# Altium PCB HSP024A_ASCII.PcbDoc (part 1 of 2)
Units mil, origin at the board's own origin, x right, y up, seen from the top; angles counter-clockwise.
Board outline 1350 x 2125 mil, 4 copper layers (Top Layer L1, GND L2, Power L3, Bottom Layer L4), stack 61.668 mil thick; 54 components, 18 nets, 93 pads, 271 vias.
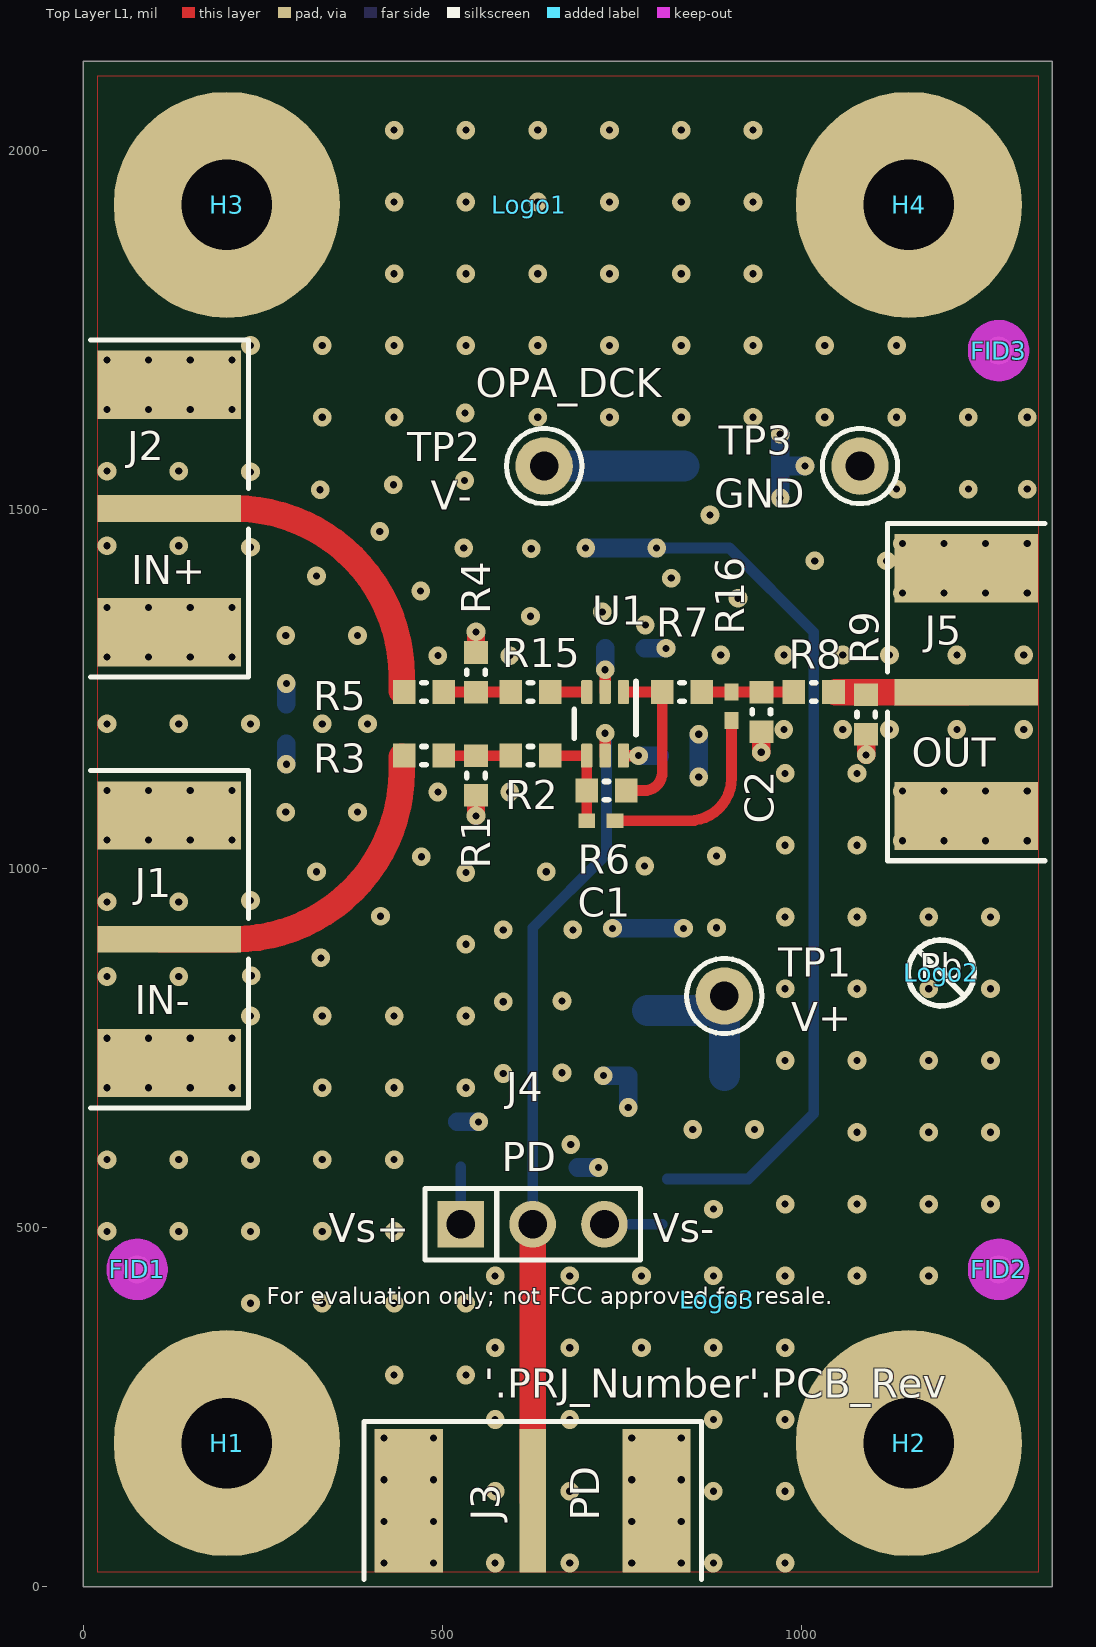
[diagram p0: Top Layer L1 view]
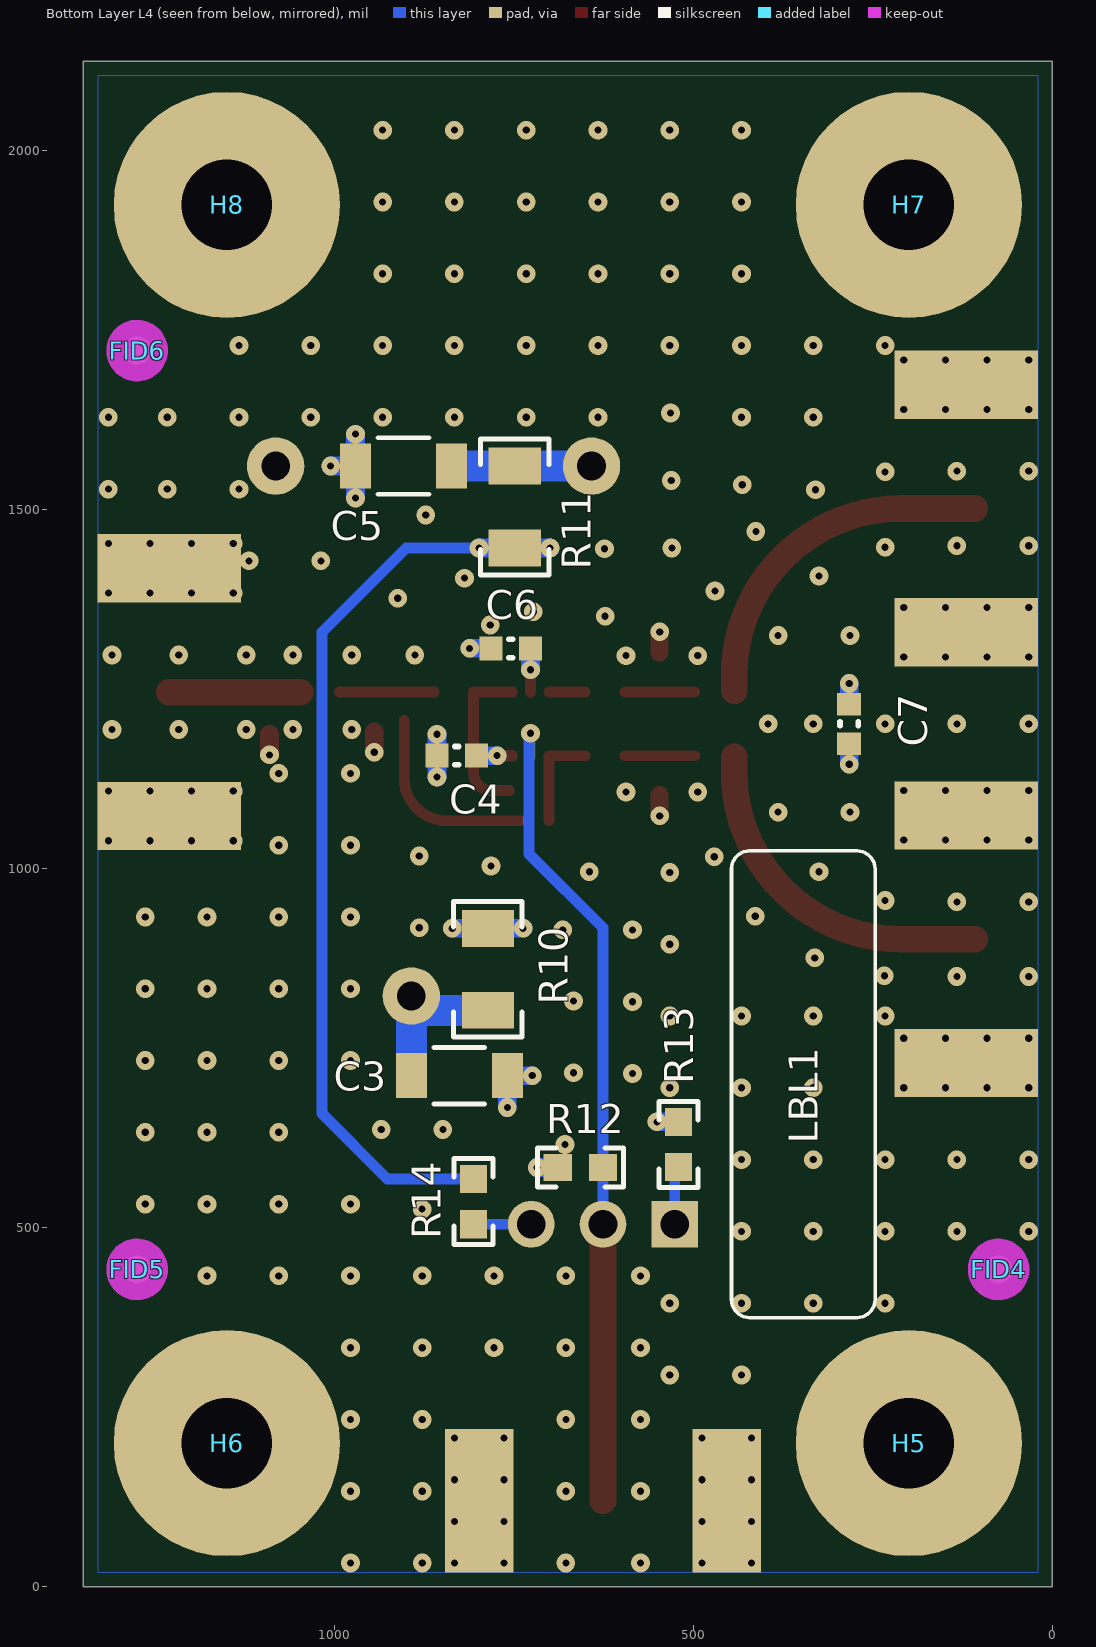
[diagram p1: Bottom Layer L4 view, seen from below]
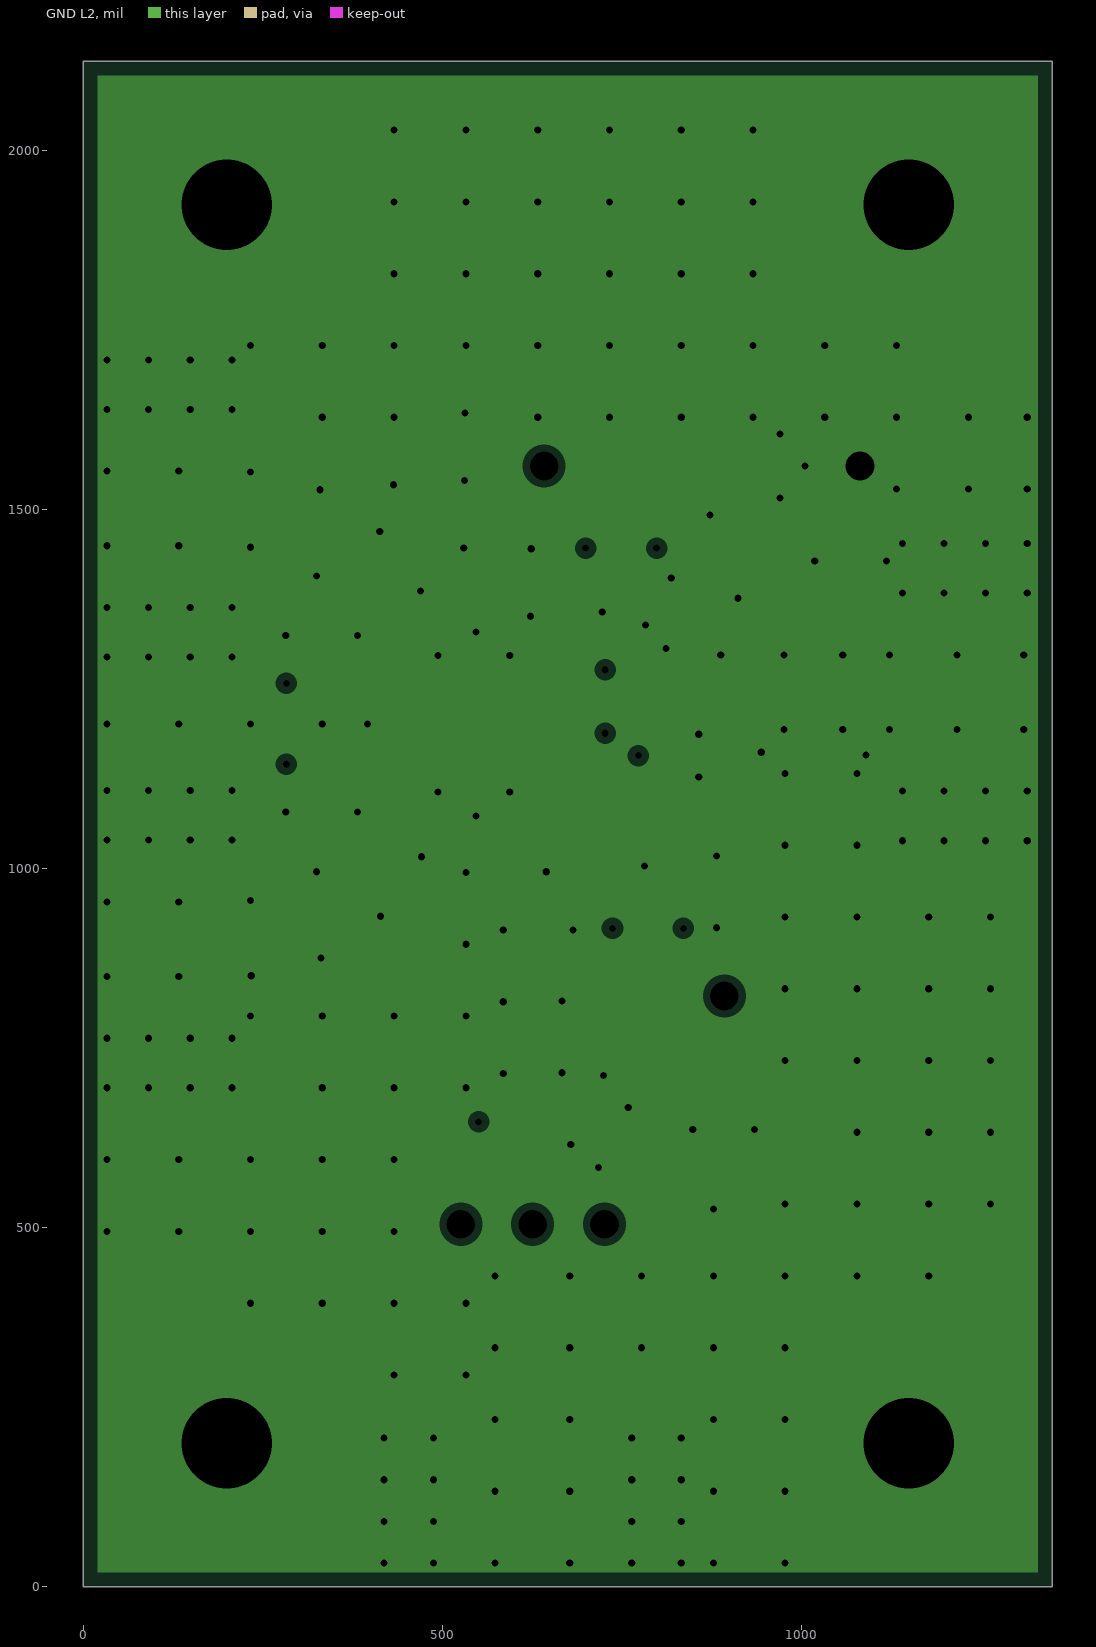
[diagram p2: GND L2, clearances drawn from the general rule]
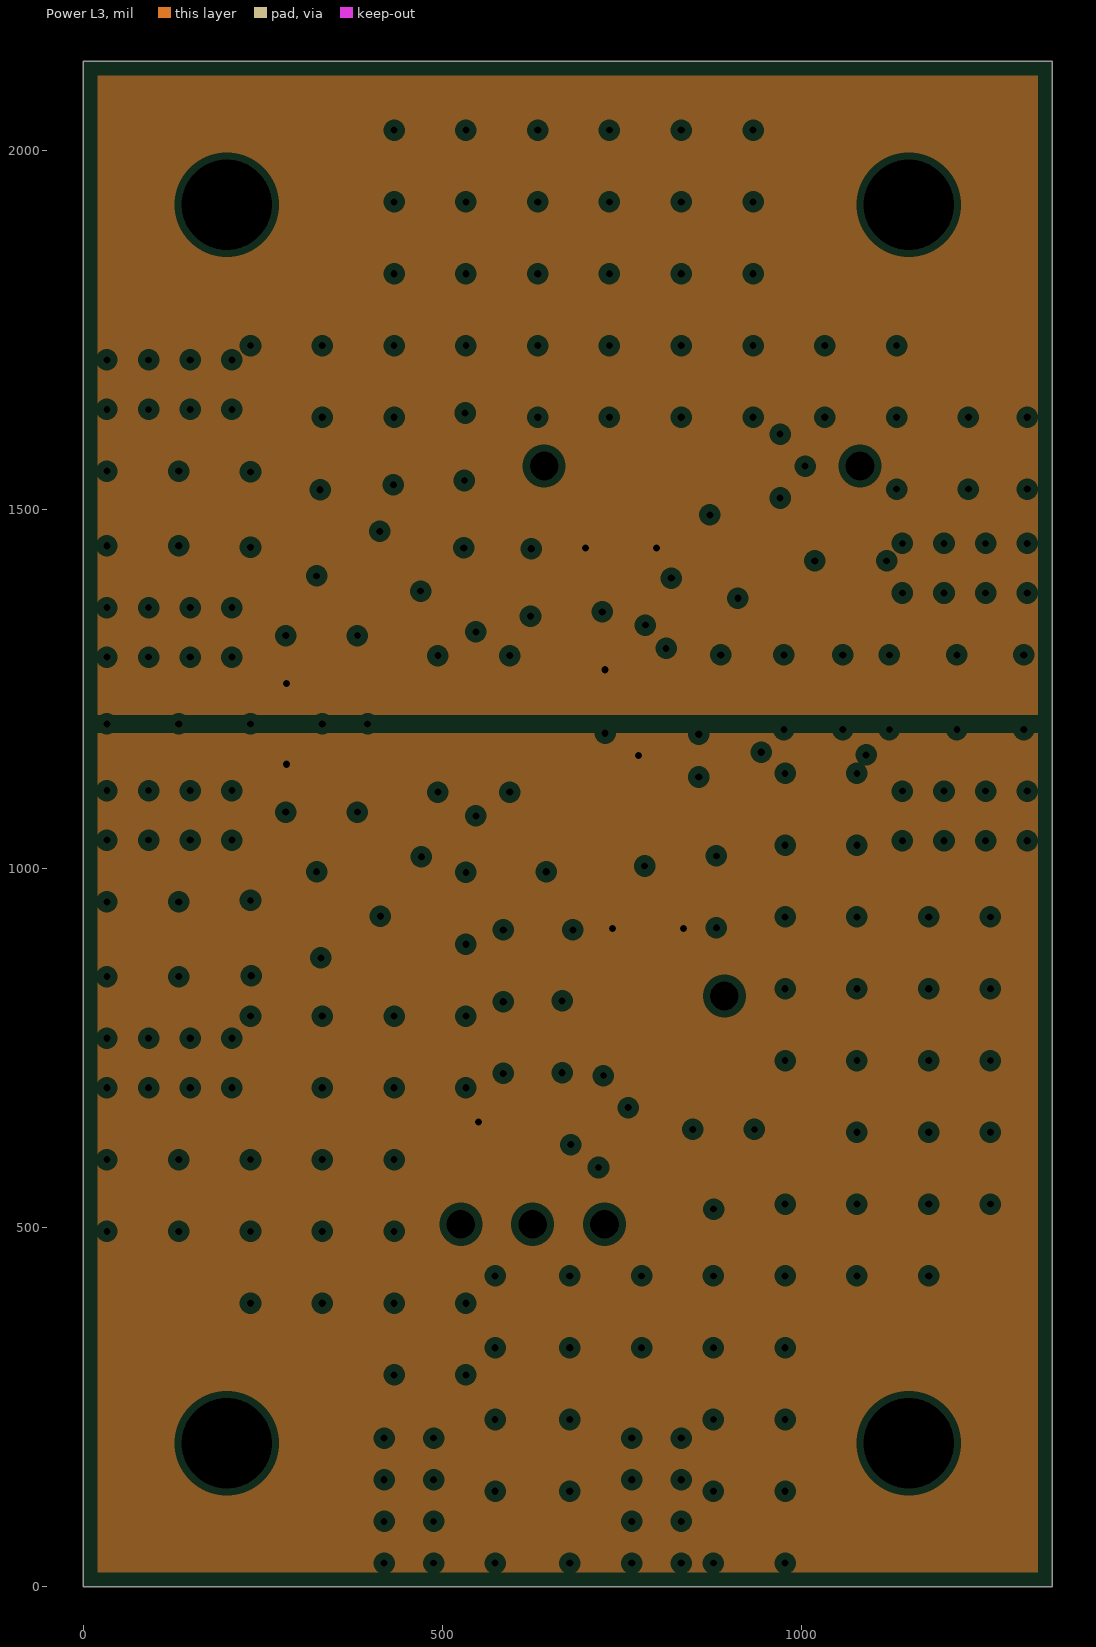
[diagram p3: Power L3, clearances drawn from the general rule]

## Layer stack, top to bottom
Top Solder: solder mask 0.4, Solder Resist, Dk 3.5
Top Layer L1: signal copper 1.417
Dielectric 1: core 21, FR-406, Dk 4.6
GND L2: plane copper 1.417, net GND
Dielectric4: prepreg 14, FR-406, Dk 4.6
Power L3: plane copper 1.417, net VS+
Dielectric5: core 21, FR-406, Dk 4.6
Bottom Layer L4: signal copper 1.417
Bottom Solder: solder mask 0.4, Solder Resist, Dk 3.5

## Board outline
0,0 1350,0 1350,2125 0,2125

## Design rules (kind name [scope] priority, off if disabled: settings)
AcuteAngle [All] p0: scope1count=1 scope1_0_kind=Board scope1_0_value=Board scope2count=1 scope2_0_kind=Board scope2_0_value=Board commentlength=0 minimum=4.50000000000000E+0001
AcuteAngle [All] p1: minimum=4.50000000000000E+0001 checktracksonly=FALSE
AssemblyTestPointUsage [All] p0: scope1count=1 scope1_0_kind=Board scope1_0_value=Board scope2count=1 scope2_0_kind=Board scope2_0_value=Board commentlength=0
AssemblyTestPointUsage [All] p1: valid=2
AssemblyTestpoint [All] p0: scope1count=1 scope1_0_kind=Board scope1_0_value=Board scope2count=1 scope2_0_kind=Board scope2_0_value=Board commentlength=0
BoardOutlineClearance [All] p0 off: scope1count=1 scope1_0_kind=Board scope1_0_value=Board scope2count=1 scope2_0_kind=Board scope2_0_value=Board commentlength=172 gap=20 // Protel DXP Scope 1 Expression Was: OnCopper and Not InComponentClass('Logo') and not InComponentClass('FiducialMark') and not InRegion(1000,500,4000,800) and not InPoly
BoardOutlineClearance BoardOutlineClearance_Poly [All] p0 off: scope1count=1 scope1_0_kind=Board scope1_0_value=Board scope2count=1 scope2_0_kind=Board scope2_0_value=Board commentlength=58 gap=20 // Protel DXP Scope 1 Expression Was: OnCopper and IsPoly
BoardOutlineClearance BoardOutlineClearance_MountingHoles [All] p0 off: scope1count=1 scope1_0_kind=Board scope1_0_value=Board scope2count=1 scope2_0_kind=Board scope2_0_value=Board commentlength=86 gap=40 // Protel DXP Scope 1 Expression Was: OnCopper and InComponentClass('Mounting Holes')
BoardOutlineClearance BoardOutlineClearance_1 [All] p0 off: scope1count=1 scope1_0_kind=Board scope1_0_value=Board scope2count=1 scope2_0_kind=Board scope2_0_value=Board commentlength=113 gap=20 // Protel DXP Scope 1 Expression Was: (InNet('NetJ1_1') OR InNet('NetJ2_1') OR InNet('NetJ5_1') OR InNet('\PD'))
BoardOutlineClearance BoardOutlineClearance_2 [All] p0: scope1count=1 scope1_0_kind=Net scope1_0_value=GND scope2count=1 scope2_0_kind=Board scope2_0_value=Board commentlength=0 gap=20
BoardOutlineClearance BoardOutlineClearance_2 [InNet('GND')] p1: gap=20 except(8: SMDPad-OutlineEdge Poly-OutlineEdge)
BoardOutlineClearance BoardOutlineClearance_1 [(InNet('NetJ1_1') OR InNet('NetJ2_1') OR InNet('NetJ5_1') OR InNet('\PD'))] p2: gap=20 except(8: SMDPad-OutlineEdge)
BoardOutlineClearance BoardOutlineClearance_MountingHoles [OnCopper and InComponentClass('Mounting Holes')] p3: gap=40
BoardOutlineClearance BoardOutlineClearance_Poly [OnCopper and IsPoly] p4: gap=20
BoardOutlineClearance [OnCopper and Not InComponentClass('Logo') and not InComponentClass('FiducialMark') and not InRegion(1000,500,4000,800) and not InPoly] p5: gap=20
Clearance [All] p0: scope1count=1 scope1_0_kind=Board scope1_0_value=Board scope2count=1 scope2_0_kind=Board scope2_0_value=Board commentlength=0 gap=7.87
Clearance Clearance_Poly [All] p0 off: scope1count=1 scope1_0_kind=Board scope1_0_value=Board scope2count=1 scope2_0_kind=Board scope2_0_value=Board commentlength=48 gap=20 // Protel DXP Scope 1 Expression Was: InPolygon
Clearance Clearance_Keepouts [All] p0 off: scope1count=1 scope1_0_kind=Board scope1_0_value=Board scope2count=1 scope2_0_kind=Board scope2_0_value=Board commentlength=99 gap=0 // Protel DXP Scope 2 Expression Was: ((IsTrack Or IsArc) And Not InPoly) And IsFree and IsKeepOut
Clearance Clearance_Keepouts [((IsTrack Or IsArc) And Not InPoly) And IsFree and IsKeepOut vs ((IsTrack Or IsArc) And Not InPoly) And IsFree and IsKeepOut] p1: gap=0
Clearance Clearance_Poly [InPolygon] p2: gap=20
Clearance [All] p3: gap=7.87
ComponentClearance [All] p0: scope1count=1 scope1_0_kind=Board scope1_0_value=Board scope2count=1 scope2_0_kind=Board scope2_0_value=Board commentlength=0 gap=30 collisioncheckmode=3
ComponentClearance ComponentClearance_THtoTH [All] p0 off: scope1count=1 scope1_0_kind=Board scope1_0_value=Board scope2count=1 scope2_0_kind=Board scope2_0_value=Board commentlength=54 gap=30 collisioncheckmode=3 // Protel DXP Scope 2 Expression Was: IsThruComponent
ComponentClearance ComponentClearance_THtoSMT [All] p0 off: scope1count=1 scope1_0_kind=Board scope1_0_value=Board scope2count=1 scope2_0_kind=Board scope2_0_value=Board commentlength=53 gap=35 collisioncheckmode=3 // Protel DXP Scope 2 Expression Was: IsSMTComponent
ComponentClearance ComponentClearance_SmallPassives [All] p0 off: scope1count=1 scope1_0_kind=Board scope1_0_value=Board scope2count=1 scope2_0_kind=Board scope2_0_value=Board commentlength=612 gap=11 collisioncheckmode=3 // Protel DXP Scope 2 Expression Was: HasFootprint('0201*') or HasFootprint('0402*') or HasFootprint('0508') or HasFootprint('0201*') or HasFootprint('0402*') or HasFootprint('0508') or HasFootprint('0603*') or HasFootprint('0612') or HasFootprint('0805*') or HasFootprint('0815*') or HasFootprint('0830*') or HasFootprint('1206*') or HasFootprint('1210*') or HasFootprint('1808*') or HasFootprint('1812*') or HasFootprint('1825*') or HasFootprint('2010*') or HasFootprint('2220*') or HasFootprint('2225*') or HasFootprint('2512*') or HasFootprint('2728*') or HasFootprint('3518*')  or HasFootprint('DCK0006A*')
ComponentClearance ComponentClearance_MountingHoles [All] p0: scope1count=1 scope1_0_kind=ComponentClass scope1_0_value="Mounting Holes" scope2count=1 scope2_0_kind=Board scope2_0_value=Board commentlength=0 gap=40 collisioncheckmode=3
ComponentClearance ComponentClearance_ScrewToNut [All] p0 off: scope1count=1 scope1_0_kind=Board scope1_0_value=Board scope2count=1 scope2_0_kind=Board scope2_0_value=Board commentlength=71 gap=5 collisioncheckmode=3 // Protel DXP Scope 2 Expression Was: (HasFootprint('Keystone_1902C'))
ComponentClearance ComponentClearance_Logo [All] p0: scope1count=1 scope1_0_kind=ComponentClass scope1_0_value=Logo scope2count=1 scope2_0_kind=Board scope2_0_value=Board commentlength=0 gap=50 collisioncheckmode=3
ComponentClearance ComponentClearance_Shunt [All] p0: scope1count=1 scope1_0_kind=ComponentClass scope1_0_value=Header scope2count=1 scope2_0_kind=ComponentClass scope2_0_value=Shunt commentlength=0 gap=0 collisioncheckmode=3
ComponentClearance ComponentClearance_MountingHoles_FiducialMarks [All] p0: scope1count=1 scope1_0_kind=ComponentClass scope1_0_value="Mounting Holes" scope2count=1 scope2_0_kind=ComponentClass scope2_0_value=FiducialMark commentlength=0 gap=50 collisioncheckmode=3
ComponentClearance ComponentClearance_MountingHoles_FiducialMarks [InComponentClass('Mounting Holes') vs InComponentClass('FiducialMark')] p1: gap=50 collisioncheckmode=3 verticalgap=10 showdistances=FALSE
ComponentClearance ComponentClearance_Shunt [InComponentClass('Header') vs InComponentClass('Shunt')] p2: gap=0 collisioncheckmode=3 verticalgap=0 showdistances=FALSE
ComponentClearance ComponentClearance_Logo [InComponentClass('Logo')] p3: gap=50 collisioncheckmode=3 verticalgap=10 showdistances=FALSE
ComponentClearance ComponentClearance_ScrewToNut [(HasFootprint('NY PMS 440 0025 PH')) vs (HasFootprint('Keystone_1902C'))] p4: gap=5 collisioncheckmode=3 verticalgap=10 showdistances=FALSE
ComponentClearance ComponentClearance_MountingHoles [InComponentClass('Mounting Holes')] p5: gap=40 collisioncheckmode=3 verticalgap=100000 showdistances=FALSE
ComponentClearance ComponentClearance_SmallPassives [HasFootprint('0201*') or HasFootprint('0402*') or HasFootprint('0508') or HasFootprint('0603*') or HasFootprint('0612') or HasFootprint('0805*') or HasFootprint('0815*') or HasFootprint('0830*') or HasFootprint('1206*') or HasFootprint('1210*') or HasFootprint('1808*') or HasFootprint('1812*') or HasFootprint('1825*') or HasFootprint('2010*') or HasFootprint('2220*') or HasFootprint('2225*') or HasFootprint('2512*') or HasFootprint('2728*') or HasFootprint('3518*')  or HasFootprint('DCK0006A*') vs HasFootprint('0201*') or HasFootprint('0402*') or HasFootprint('0508') or HasFootprint('0201*') or HasFootprint('0402*') or HasFootprint('0508') or HasFootprint('0603*') or HasFootprint('0612') or HasFootprint('0805*') or HasFootprint('0815*') or HasFootprint('0830*') or HasFootprint('1206*') or HasFootprint('1210*') or HasFootprint('1808*') or HasFootprint('1812*') or HasFootprint('1825*') or HasFootprint('2010*') or HasFootprint('2220*') or HasFootprint('2225*') or HasFootprint('2512*') or HasFootprint('2728*') or HasFootprint('3518*')  or HasFootprint('DCK0006A*')] p6: gap=11 collisioncheckmode=3 verticalgap=10 showdistances=FALSE
ComponentClearance ComponentClearance_THtoSMT [IsThruComponent vs IsSMTComponent] p7: gap=35 collisioncheckmode=3 verticalgap=30 showdistances=FALSE
ComponentClearance ComponentClearance_THtoTH [IsThruComponent vs IsThruComponent] p8: gap=30 collisioncheckmode=3 verticalgap=30 showdistances=FALSE
ComponentClearance [All] p9: gap=30 collisioncheckmode=3 verticalgap=10 showdistances=FALSE
DiffPairsRouting [All] p0: scope1count=1 scope1_0_kind=Board scope1_0_value=Board scope2count=1 scope2_0_kind=Board scope2_0_value=Board commentlength=0
DiffPairsRouting [All] p1: maxlimit=100 minlimit=10 mostfreqgap=10 toplayer_minwidth=15 toplayer_maxwidth=15 toplayer_prefwidth=15 bottomlayer_minwidth=15 bottomlayer_maxwidth=15 bottomlayer_prefwidth=15 maxuncoupledlength=1000
FabricationTestPointUsage TestPointUsage [All] p0: scope1count=1 scope1_0_kind=Board scope1_0_value=Board scope2count=1 scope2_0_kind=Board scope2_0_value=Board commentlength=0 valid=2 allowmultiple=FALSE
FabricationTestPointUsage TestPointUsage [All] p1: valid=2 allowmultiple=FALSE
FabricationTestpoint Testpoint [All] p0: scope1count=1 scope1_0_kind=Board scope1_0_value=Board scope2count=1 scope2_0_kind=Board scope2_0_value=Board commentlength=0 side=3 testpointundercomponent=TRUE minsize=40 maxsize=100 preferedsize=60 minholesize=0 maxholesize=40 preferedholesize=32 testpointgrid=1
FabricationTestpoint Testpoint [All] p1: side=3 testpointundercomponent=TRUE minsize=40 maxsize=100 preferedsize=60 minholesize=0 maxholesize=40 preferedholesize=32 testpointgrid=1 allowsidetop=TRUE allowsidebottom=TRUE usegrid=TRUE gridtolerance=0.01
FanoutControl Fanout_Small [All] p0 off: scope1count=1 scope1_0_kind=Board scope1_0_value=Board scope2count=1 scope2_0_kind=Board scope2_0_value=Board commentlength=84 // Protel DXP Scope 1 Expression Was: (CompPinCount < 5)   Fanout_Small (Default Rule)
FanoutControl Fanout_Default [All] p0: scope1count=1 scope1_0_kind=Board scope1_0_value=Board scope2count=1 scope2_0_kind=Board scope2_0_value=Board commentlength=30 // Fanout_Default (Default Rule)
FanoutControl Fanout_SOIC [All] p0 off: scope1count=1 scope1_0_kind=Board scope1_0_value=Board scope2count=1 scope2_0_kind=Board scope2_0_value=Board commentlength=71 // Protel DXP Scope 1 Expression Was: IsSOIC   Fanout_SOIC (Default Rule)
FanoutControl Fanout_BGA [All] p0 off: scope1count=1 scope1_0_kind=Board scope1_0_value=Board scope2count=1 scope2_0_kind=Board scope2_0_value=Board commentlength=69 // Protel DXP Scope 1 Expression Was: IsBGA   Fanout_BGA (Default Rule)
FanoutControl Fanout_LCC [All] p0 off: scope1count=1 scope1_0_kind=Board scope1_0_value=Board scope2count=1 scope2_0_kind=Board scope2_0_value=Board commentlength=69 // Protel DXP Scope 1 Expression Was: IsLCC   Fanout_LCC (Default Rule)
FanoutControl Fanout_LCC [IsLCC] p1: bgadir=Out bgaviamode=Centered fanoutstyle=Auto fanoutdirection=Alternating viagrid=1 // Fanout_LCC (Default Rule)
FanoutControl Fanout_BGA [IsBGA] p2: bgadir=Out bgaviamode=Centered fanoutstyle=Auto fanoutdirection=Alternating viagrid=1 // Fanout_BGA (Default Rule)
FanoutControl Fanout_Default [All] p4: bgadir=Out bgaviamode=Centered fanoutstyle=Auto fanoutdirection=Alternating viagrid=1 // Fanout_Default (Default Rule)
FanoutControl Fanout_Small [(CompPinCount < 5)] p5: bgadir=Out bgaviamode=Centered fanoutstyle=Auto fanoutdirection=OutThenIn viagrid=1 // Fanout_Small (Default Rule)
Height [All] p0: scope1count=1 scope1_0_kind=Board scope1_0_value=Board scope2count=1 scope2_0_kind=Board scope2_0_value=Board commentlength=0
HoleSize HoleSize_1 [All] p0: scope1count=1 scope1_0_kind=Board scope1_0_value=Board scope2count=1 scope2_0_kind=Board scope2_0_value=Board commentlength=0 absolutevalues=TRUE maxlimit=251 minlimit=7.87 maxpercent=80.000 minpercent=20.000
HoleSize HoleSize_1 [All] p1: absolutevalues=TRUE maxlimit=251 minlimit=7.87 maxpercent=80.000 minpercent=20.000
HoleToHoleClearance [All] p0: scope1count=1 scope1_0_kind=Board scope1_0_value=Board scope2count=1 scope2_0_kind=Board scope2_0_value=Board commentlength=0
LayerPairs [All] p0: scope1count=1 scope1_0_kind=Board scope1_0_value=Board scope2count=1 scope2_0_kind=Board scope2_0_value=Board commentlength=0 enforce=TRUE
MinimumAnnularRing [All] p0: scope1count=1 scope1_0_kind=Board scope1_0_value=Board scope2count=1 scope2_0_kind=Board scope2_0_value=Board commentlength=0 minimumring=8
MinimumAnnularRing MinimumAnnularRing_ThermalPadVias [All] p0 off: scope1count=1 scope1_0_kind=Board scope1_0_value=Board scope2count=1 scope2_0_kind=Board scope2_0_value=Board commentlength=63 minimumring=5.91 // Protel DXP Scope 1 Expression Was: IsVia and InAnyComponent
MinimumAnnularRing MinimumAnnularRing_ThermalPadVias [IsVia and InAnyComponent] p1: minimumring=5.91
MinimumAnnularRing [All] p2: minimumring=8
MinimumSolderMaskSliver [All] p0: scope1count=1 scope1_0_kind=Board scope1_0_value=Board scope2count=1 scope2_0_kind=Board scope2_0_value=Board commentlength=0
MinimumSolderMaskSliver MinimumSolderMaskSliver_Logo [All] p0: scope1count=1 scope1_0_kind=ComponentClass scope1_0_value=Logo scope2count=1 scope2_0_kind=ComponentClass scope2_0_value=Logo commentlength=0
MinimumSolderMaskSliver MinimumSolderMaskSliver_Logo [InComponentClass('Logo') vs InComponentClass('Logo')] p1: minsoldermaskwidth=0.7
MinimumSolderMaskSliver [All] p2: minsoldermaskwidth=3.94
NetAntennae [All] p0: scope1count=1 scope1_0_kind=Board scope1_0_value=Board scope2count=1 scope2_0_kind=Board scope2_0_value=Board commentlength=0
PasteMaskExpansion [All] p0: scope1count=1 scope1_0_kind=Board scope1_0_value=Board scope2count=1 scope2_0_kind=Board scope2_0_value=Board commentlength=0 expansion=0
PlaneClearance [All] p0: scope1count=1 scope1_0_kind=Board scope1_0_value=Board scope2count=1 scope2_0_kind=Board scope2_0_value=Board commentlength=0 clearance=10
PlaneClearance [All] p1: clearance=10
PlaneConnect [All] p0: scope1count=1 scope1_0_kind=Board scope1_0_value=Board scope2count=1 scope2_0_kind=Board scope2_0_value=Board commentlength=0 planeconnectstyle=Direct reliefexpansion=10 reliefentries=4 reliefconductorwidth=10 reliefairgap=10
PlaneConnect [All] p1: planeconnectstyle=Direct reliefexpansion=10 reliefentries=4 reliefconductorwidth=10 reliefairgap=10
PolygonConnect [All] p0: scope1count=1 scope1_0_kind=Board scope1_0_value=Board scope2count=1 scope2_0_kind=Board scope2_0_value=Board commentlength=0 connectstyle=Direct reliefconductorwidth=10 reliefentries=4 polygonreliefangle="90 Angle"
PolygonConnect [All] p1: connectstyle=Direct reliefconductorwidth=10 reliefentries=4 polygonreliefangle="90 Angle" airgapwidth=10
RoutingCorners [All] p0: scope1count=1 scope1_0_kind=Board scope1_0_value=Board scope2count=1 scope2_0_kind=Board scope2_0_value=Board commentlength=0 cornerstyle=45-Degree minsetback=100 maxsetback=100
RoutingLayers [All] p0: scope1count=1 scope1_0_kind=Board scope1_0_value=Board scope2count=1 scope2_0_kind=Board scope2_0_value=Board commentlength=0 top layer=Automatic bottom layer=Automatic
RoutingPriority [All] p0: scope1count=1 scope1_0_kind=Board scope1_0_value=Board scope2count=1 scope2_0_kind=Board scope2_0_value=Board commentlength=0
RoutingTopology [All] p0: scope1count=1 scope1_0_kind=Board scope1_0_value=Board scope2count=1 scope2_0_kind=Board scope2_0_value=Board commentlength=0 topology=Shortest
RoutingVias [All] p0: scope1count=1 scope1_0_kind=Board scope1_0_value=Board scope2count=1 scope2_0_kind=Board scope2_0_value=Board commentlength=0 holewidth=16 width=34 viastyle="Through Hole" minholewidth=7.87 minwidth=26 maxholewidth=40 maxwidth=65
RoutingVias ThermalPadVias [All] p0 off: scope1count=1 scope1_0_kind=Board scope1_0_value=Board scope2count=1 scope2_0_kind=Board scope2_0_value=Board commentlength=63 holewidth=7.87 width=19.68 viastyle="Through Hole" minholewidth=7.87 minwidth=19.68 maxholewidth=12.99 maxwidth=23.62 // Protel DXP Scope 1 Expression Was: IsVia and InAnyComponent
RoutingVias ThermalPadVias [IsVia and InAnyComponent] p1: holewidth=7.87 width=19.68 viastyle="Through Hole" minholewidth=7.87 minwidth=19.68 maxholewidth=12.99 maxwidth=23.62
RoutingVias [All] p2: holewidth=16 width=34 viastyle="Through Hole" minholewidth=7.87 minwidth=26 maxholewidth=40 maxwidth=65
ShortCircuit [All] p0: scope1count=1 scope1_0_kind=Board scope1_0_value=Board scope2count=1 scope2_0_kind=Board scope2_0_value=Board commentlength=0 allowed=FALSE
SilkToBoardRegionClearance [All] p0: scope1count=1 scope1_0_kind=Board scope1_0_value=Board scope2count=1 scope2_0_kind=Board scope2_0_value=Board commentlength=0
SilkToSilkClearance [All] p0: scope1count=1 scope1_0_kind=Board scope1_0_value=Board scope2count=1 scope2_0_kind=Board scope2_0_value=Board commentlength=0
SilkToSilkClearance SilkToSilkClearance_Pb-FreeLogo [All] p0 off: scope1count=1 scope1_0_kind=Board scope1_0_value=Board scope2count=1 scope2_0_kind=Board scope2_0_value=Board commentlength=120 // Protel DXP Scope 2 Expression Was: (HasFootprint('Pb-Free_Overlay_Medium') OR HasFootprint('Pb-Free_Overlay_Small'))
SilkToSilkClearance SilkToSilkClearance_Pb-FreeLogo [(HasFootprint('Pb-Free_Overlay_Medium') OR HasFootprint('Pb-Free_Overlay_Small')) vs (HasFootprint('Pb-Free_Overlay_Medium') OR HasFootprint('Pb-Free_Overlay_Small'))] p1: silktosilkclearance=0
SilkToSilkClearance [All] p2: silktosilkclearance=4
SilkToSolderMaskClearance "Silk to Solder Mask Opening" [All] p0: scope1count=1 scope1_0_kind=Board scope1_0_value=Board scope2count=1 scope2_0_kind=Board scope2_0_value=Board commentlength=0
SilkToSolderMaskClearance SilkToComponentPadClearance [All] p0 off: scope1count=1 scope1_0_kind=Board scope1_0_value=Board scope2count=1 scope2_0_kind=Board scope2_0_value=Board commentlength=63 // Protel DXP Scope 1 Expression Was: IsPad and InAnycomponent
SilkToSolderMaskClearance SilkToComponentPadClearance [IsPad and InAnycomponent] p1: minsilkscreentomaskgap=5 clearancetoexposedcopper=TRUE
SilkToSolderMaskClearance "Silk to Solder Mask Opening" [All] p2: minsilkscreentomaskgap=4 clearancetoexposedcopper=FALSE
SolderMaskExpansion [All] p0: scope1count=1 scope1_0_kind=Board scope1_0_value=Board scope2count=1 scope2_0_kind=Board scope2_0_value=Board commentlength=0 expansion=1.97
SolderMaskExpansion [All] p1: expansion=1.97
UnRoutedNet [All] p0: scope1count=1 scope1_0_kind=Board scope1_0_value=Board scope2count=1 scope2_0_kind=Board scope2_0_value=Board commentlength=0
UnpouredPolygon [All] p0: scope1count=1 scope1_0_kind=Board scope1_0_value=Board scope2count=1 scope2_0_kind=Board scope2_0_value=Board commentlength=0
Width [All] p0: scope1count=1 scope1_0_kind=Board scope1_0_value=Board scope2count=1 scope2_0_kind=Board scope2_0_value=Board commentlength=0 maxlimit=100 minlimit=6 preferedwidth=10
Width [All] p1: maxlimit=100 minlimit=6 preferedwidth=10 checkconnectedcopper=TRUE
15 further rules are at their usual default settings.

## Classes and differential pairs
component class "Mounting Holes": H1 H2 H3 H4
component class Label: LBL1
component class Header: J4
component class AssemblyNote: ZZ1 ZZ2 ZZ3 ZZ4
component class FiducialMark: FID1 FID2 FID3 FID4 FID5 FID6
component class Logo: Logo1

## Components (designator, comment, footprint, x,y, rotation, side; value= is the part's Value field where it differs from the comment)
C1 "C1005C0G1HR75C050BA" 0402L 721.06,1067 r180 top
C2 "C0603C209C5GACTU" 0603L 944.53,1218.73 r270 top
C3 "C3216X6S1V106K160AC" 1206_180 826.07,712 r180 bottom
C4 "06031C103JAT2A" 0603L 829.73,1157.71 r0 bottom
C5 "C3216X6S1V106K160AC" 1206_180 903.85,1561.09 r0 bottom
C6 "06031C103JAT2A" 0603L 754.52,1307.12 r0 bottom
C7 "06031C103JAT2A" 0603L 283,1202 r270 bottom
FID1 "Fiducial" Fiducial10-20 75,442 r0 top
FID2 "Fiducial" Fiducial10-20 1275,442 r0 top
FID3 "Fiducial" Fiducial10-20 1275,1722 r0 top
FID4 "Fiducial" Fiducial10-20 75,442 r180 bottom
FID5 "Fiducial" Fiducial10-20 1275,442 r180 bottom
FID6 "Fiducial" Fiducial10-20 1275,1722 r180 bottom
H1 "NY PMS 440 0025 PH" "NY PMS 440 0025 PH" 200,200 r0 top
H2 "NY PMS 440 0025 PH" "NY PMS 440 0025 PH" 1150,200 r0 top
H3 "NY PMS 440 0025 PH" "NY PMS 440 0025 PH" 200,1925 r0 top
H4 "NY PMS 440 0025 PH" "NY PMS 440 0025 PH" 1150,1925 r0 top
H5 "1902C" Keystone_1902C 200.36,200 r180 bottom
H6 "1902C" Keystone_1902C 1150,200 r180 bottom
H7 "1902C" Keystone_1902C 200.36,1925 r180 bottom
H8 "1902C" Keystone_1902C 1150,1925 r180 bottom
J1 "IN-" Emerson_142-0701-851 10,902 r90 top
J2 "IN+" Emerson_142-0701-851 10,1502 r90 top
J3 "PD" Emerson_142-0701-851 626,10 r180 top
J4 "PD" TSW-103-07-G-S 626,505 r0 top
J5 "OUT" Emerson_142-0701-851 1340,1246.29 r270 top
LBL1 "Size: 0.65\" x 0.20 \"" Label_650x200 347,700 r270 bottom
Logo1 "Texas Instruments" TI_Symbol_Overlay_Medium 621,1925 r0 top
Logo2 "Pb-Free Symbol" Pb-Free_Overlay_Small 1195,855 r0 top
Logo3 "FCC disclaimer" FCC_disclaimer 883,400 r0 top
R1 "CRCW060352R3FKEA" 0603L 547,1130.15 r90 top
R2 "RT0603DRE07976RL" 0603L 623,1157.71 r180 top
R3 "CRCW06030000Z0EA" 0603L 474.65,1157.71 r0 top
R4 "CRCW060350R0FKEA" 0603L 547,1273.85 r270 top
R5 "CRCW06030000Z0EA" 0603L 474.65,1246.29 r0 top
R6 "CRCW06030000Z0EA" 0603L 728.93,1109 r0 top
R7 "CRCW06031K96FKEA" 0603L 834,1246.29 r180 top
R8 "CRCW06030000Z0EA" 0603L 1017.53,1246.29 r0 top
R9 "CRCW060351R1FKEA" 0603L 1090.53,1215.09 r90 top
R10 "RC1206JR-070RL" 1206 786.32,860 r90 bottom
R11 "RC1206JR-070RL" 1206 748.92,1504 r270 bottom
R12 "CRCW060350R0FKEA" 0603 657.5,584 r180 bottom
R13 "CRCW06031K00FKEA" 0603 521,616.05 r90 bottom
R14 "CRCW06031K00FKEA" 0603 806.46,536.5 r270 bottom
R15 "CRCW06030000Z0EA" 0603L 623,1246.29 r180 top
R16 "CRCW04021K00FKED" 0402L 903,1226.61 r90 top
TP1 "V+" Keystone5000 893,822.91 r0 top
TP2 "V-" Keystone5004 642,1561.09 r0 top
TP3 "GND" Keystone5001 1082,1561.09 r0 top
U1 "TLV3011AIDCKR" DCK0006A_N 726.96,1202 r270 top
ZZ1 "This Assembly Note is for PCB labels only" AssemblyNoteLabel 185,2688 r0 top
ZZ2 "These assemblies are ESD sensitive, ESD precautions shall be observed." AssemblyNote 185,2579.11 r0 top
ZZ3 "These assemblies must be clean and free from flux and all contaminants. Use of no clean flux is not acceptable." AssemblyNote 185,2490.56 r0 top
ZZ4 "These assemblies must comply with workmanship standards IPC-A-610 Class 2, unless otherwise specified." AssemblyNote 185,2402 r0 top

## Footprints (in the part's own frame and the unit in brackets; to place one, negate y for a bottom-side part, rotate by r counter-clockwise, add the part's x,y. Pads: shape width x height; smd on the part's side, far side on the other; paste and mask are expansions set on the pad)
0402L [mm] "0402 from SM-752 data"
  rect 0.6x0.5 smd: 1(-0.5,0) 2(0.5,0)
0603 [mm] "0603 from SM-752 data"
  rect 1x0.95 smd: 1(-0.8,0) 2(0.8,0)
  silkscreen extent -1.52,-0.69 1.52,0.69
0603L [mm] "0603 from SM-752 data"
  rect 0.8x0.85 smd: 1(-0.7,0) 2(0.7,0)
  silkscreen extent -0.07,-0.33 0.07,0.33
1206 [mm] "1206 from SM-752 data"
  rect 1.3x1.85 smd: 1(-1.45,0) 2(1.45,0)
  silkscreen extent -2.4,-1.21 2.4,1.21
1206_180 [mm] "1206_180"
  rect 1.1x1.6 smd: 1(-1.7,0) 2(1.7,0)
  silkscreen extent -0.9,-1 0.9,1
AssemblyNote [mil] "Assembly Note"
AssemblyNoteLabel [mil] "Assembly Note for PCB Labels"
DCK0006A_N [mm] "SOT23, 6-Leads, Body 2x1.3mm, Pitch 0.65mm, Lead Span 2.1mm, IPC Medium Density"
  rrect25% 0.85x0.4 smd: 1(-1.125,0.65) 2(-1.125,0) 3(-1.125,-0.65) 4(1.125,-0.65) 5(1.125,0) 6(1.125,0.65)
  silkscreen extent -1.5,-1.09 0.51,1.09
Emerson_142-0701-851 [mil] "Johnson Components"
  rect 37x200 smd: 1(0,-110)
  rect 95x200 smd: 2(-172.5,-110) 3(172.5,-110)
  rect 95x200 smd far side: 4(172.5,-110) 5(-172.5,-110)
  silkscreen extent -235,-220 235,0
FCC_disclaimer [mil]
Fiducial10-20 [mm]
  round 1 smd mask+0: 1(0,0)
  Top Layer L1 keep-out circle w1.178: c0,0 r0.5
Keystone5000 [mil] "For Keystone 500x miniature loop terminals"
  round 80 hole 40: 1(0,0)
  silkscreen extent -52,-52 52,52
Keystone5001 [mil] "For Keystone 500x miniature loop terminals"
  round 80 hole 40: 1(0,0)
  silkscreen extent -52,-52 52,52
Keystone5004 [mil] "For Keystone 500x miniature loop terminals"
  round 80 hole 40: 1(0,0)
  silkscreen extent -52,-52 52,52
Keystone_1902C [mil] "Hex Standoff, 4-40 threaded, nylon"
  round 1 on Mech4: 0(0,0)
Label_650x200 [mil] "Thermal Transfer Label"
  round 1 on Mech14: 0(0,0)
  silkscreen extent -325,-100 325,100
"NY PMS 440 0025 PH" [mm] "4-40 nylon screw and mounting hole"
  round 8 hole 3.2: 1(0,0)
Pb-Free_Overlay_Small [mil]
  silkscreen extent -46,-46 46,46
TI_Symbol_Overlay_Medium [mil]
TSW-103-07-G-S [mm] "Samtec 100mil, 1x3, 230 mil above insulator"
  rect 1.65x1.65 hole 1.016: 1(-2.54,0)
  round 1.65 hole 1.016: 2(0,0) 3(2.54,0)
  silkscreen extent -3.81,-1.27 3.81,1.27

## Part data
C1: "CAP, CERM, 0.75pF, 50 V, +/- 33%, C0G/NP0, 0402"
C2: "CAP, CERM, 2 pF, 50 V, +/- 12.5%, C0G/NP0, 0603"
C3 C5: "CAP, CERM, 10 µF, 35 V, +/- 10%, X6S, 1206"
C4 C6 C7: "CAP, CERM, 0.01 µF, 100 V, +/- 5%, X7R, 0603"
FID1 FID2 FID3 FID4 FID5 FID6: "Fiducial mark.  There is nothing to buy or mount."
H1 H2 H3 H4: "Machine Screw, Round, #4-40 x 1/4, Nylon, Philips panhead"
H5 H6 H7 H8: "Standoff, Hex, 0.5\"L #4-40 Nylon"
J1 J2 J3 J5: library part 142-0701-851, "Connector, End launch SMA, 50 ohm, SMT"
J4: library part TSW-103-07-G-S, "Header, 100mil, 3x1, Gold, TH"
LBL1: library part THT-14-423-10, "Thermal Transfer Printable Labels, 0.650\" W x 0.200\" H - 10,000 per roll"
Logo1: library part TI_Logo, "Texas Instrument Corporate Signature"
Logo2: library part Pb-Free
Logo3: library part FCC_disclaimer, "FCC_disclaimer"
R1: "RES, 52.3, 1%, 0.1 W, 0603"
R2: "RES, 976, 0.5%, 0.1 W, 0603"
R3 R5 R6 R8 R15: "RES, 0, 5%, 0.1 W, 0603"
R4 R12: "RES, 50, 1%, 0.1 W, 0603"
R7: "RES, 1.96 k, 1%, 0.1 W, 0603"
R9: "RES, 51.1, 1%, 0.1 W, 0603"
R10 R11: "RES, 0, 5%, 0.25 W, 1206"
R13 R14: "RES, 1.00 k, 1%, 0.1 W, 0603"
R16: "RES, 1.00 k, 1%, 0.063 W, 0402"
TP1: library part 5000, "Test Point, Miniature, Red, TH"
TP2: library part 5004, "Test Point, Miniature, Yellow, TH"
TP3: library part 5001, "Test Point, Miniature, Black, TH"
U1: "Low Power Open Drain Output Comparator with Voltage Reference, DCK0006A (SOT-SC70-6)"
ZZ1: library part AssemblyNoteLabel
ZZ2 ZZ3 ZZ4: library part AssemblyNote

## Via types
v1: diameter 26, hole 10, Top Layer L1 to Bottom Layer L4, tented both sides, 271 vias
